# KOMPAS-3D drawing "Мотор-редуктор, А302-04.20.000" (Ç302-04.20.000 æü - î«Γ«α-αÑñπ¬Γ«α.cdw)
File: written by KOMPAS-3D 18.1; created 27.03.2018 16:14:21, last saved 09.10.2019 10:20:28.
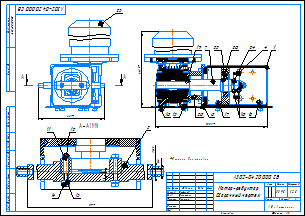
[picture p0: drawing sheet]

Sheet 1: A3, landscape

Document properties: Автор: Милов; Полное имя файла: А302-00.20.000  - Мотор-редуктор.spw; Масса: 33.945

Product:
- Part/product: Мотор-редуктор  | designation А302-04.20.000  | pos. 0
    Масса: 33.945
    Раздел спецификации: Сборочные единицы
    Форматы листов документа: 2xA3
    Примечание: @100~)2xA3
    source file: А302-04.20.000 СБ - Мотор-редуктор.cdw
  - Component [standard]: Кольцо A40.65Г ГОСТ 13942-86  | pos. 51  | Материал: Сталь 65Г ГОСТ 14959-79 (density 1000 kg/m3); Масса: 0.007267; Раздел спецификации: Стандартные изделия; additional columns: Сталь 65Г ГОСТ 14959-79
  - Component [detail]: Подшипник 80х40х18 6208-2RS1 SKF  | pos. 54  | Масса: 0.504792; Раздел спецификации: Стандартные изделия; source file: ..\..\..\..\1 ПКИ 3D\1 Крепеж стандартный\Подшипник\Подшипник 80х40х18 6208-2RS1 SKF.m3d
  - Component [standard]: Винт с цилиндрической головкой и шестигранным углублением под ключ ГОСТ Р ИСО 4762-М8 x 25-A2-70  | pos. 150  | Материал: Нержавеющая сталь (density 1000 kg/m3); Масса: 0.015; Раздел спецификации: Стандартные изделия; Рассекать на разрезах: no; additional columns: ГОСТ Р ИСО 4762-2012; М8 x 25 - A2-70
  - Component [standard]: Винт с цилиндрической головкой и шестигранным углублением под ключ ГОСТ Р ИСО 4762-М8 x 25-A2-70  | pos. 149  | Материал: Нержавеющая сталь (density 1000 kg/m3); Масса: 0.015; Раздел спецификации: Стандартные изделия; Рассекать на разрезах: no; additional columns: ГОСТ Р ИСО 4762-2012; М8 x 25 - A2-70
  - Component [standard]: Винт с цилиндрической головкой и шестигранным углублением под ключ ГОСТ Р ИСО 4762-М8 x 25-A2-70  | pos. 147  | Материал: Нержавеющая сталь (density 1000 kg/m3); Масса: 0.015; Раздел спецификации: Стандартные изделия; Рассекать на разрезах: no; additional columns: ГОСТ Р ИСО 4762-2012; М8 x 25 - A2-70
  - Component [standard]: Винт с цилиндрической головкой и шестигранным углублением под ключ ГОСТ Р ИСО 4762-М8 x 25-A2-70  | pos. 146  | Материал: Нержавеющая сталь (density 1000 kg/m3); Масса: 0.015; Раздел спецификации: Стандартные изделия; Рассекать на разрезах: no; additional columns: ГОСТ Р ИСО 4762-2012; М8 x 25 - A2-70
  - Component [standard]: Винт с цилиндрической головкой и шестигранным углублением под ключ ГОСТ Р ИСО 4762-М8 x 25-A2-70  | pos. 140  | Материал: Нержавеющая сталь (density 1000 kg/m3); Масса: 0.015; Раздел спецификации: Стандартные изделия; Рассекать на разрезах: no; additional columns: ГОСТ Р ИСО 4762-2012; М8 x 25 - A2-70
  - Component [standard]: Винт с цилиндрической головкой и шестигранным углублением под ключ ГОСТ Р ИСО 4762-М8 x 25-A2-70  | pos. 139  | Материал: Нержавеющая сталь (density 1000 kg/m3); Масса: 0.015; Раздел спецификации: Стандартные изделия; Рассекать на разрезах: no; additional columns: ГОСТ Р ИСО 4762-2012; М8 x 25 - A2-70
  - Component [standard]: Винт с цилиндрической головкой и шестигранным углублением под ключ ГОСТ Р ИСО 4762-М8 x 25-A2-70  | pos. 138  | Материал: Нержавеющая сталь (density 1000 kg/m3); Масса: 0.015; Раздел спецификации: Стандартные изделия; Рассекать на разрезах: no; additional columns: ГОСТ Р ИСО 4762-2012; М8 x 25 - A2-70
  - Component [standard]: Винт с цилиндрической головкой и шестигранным углублением под ключ ГОСТ Р ИСО 4762-М8 x 25-A2-70  | pos. 137  | Материал: Нержавеющая сталь (density 1000 kg/m3); Масса: 0.015; Раздел спецификации: Стандартные изделия; Рассекать на разрезах: no; additional columns: ГОСТ Р ИСО 4762-2012; М8 x 25 - A2-70
  - Component [standard]: Винт с цилиндрической головкой и шестигранным углублением под ключ ГОСТ Р ИСО 4762-М8 x 25-A2-70  | pos. 129  | Материал: Нержавеющая сталь (density 1000 kg/m3); Масса: 0.015; Раздел спецификации: Стандартные изделия; Рассекать на разрезах: no; additional columns: ГОСТ Р ИСО 4762-2012; М8 x 25 - A2-70
  - Component [standard]: Винт с цилиндрической головкой и шестигранным углублением под ключ ГОСТ Р ИСО 4762-М8 x 25-A2-70  | pos. 128  | Материал: Нержавеющая сталь (density 1000 kg/m3); Масса: 0.015; Раздел спецификации: Стандартные изделия; Рассекать на разрезах: no; additional columns: ГОСТ Р ИСО 4762-2012; М8 x 25 - A2-70
  - Component [standard]: Гайка М6-6H.21.12Х18Н10Т ГОСТ 5915-70  | qty 2  | Материал: Сталь 12Х18Н10Т ГОСТ 5632-72 (density 1000 kg/m3); Масса: 0.002573; Раздел спецификации: Стандартные изделия; Рассекать на разрезах: no
  - Component [standard]: Шайба 6 30Х13 019 ГОСТ 6402-70  | qty 2  | Материал: Сталь 30Х13 ГОСТ 5632-72 (density 1000 kg/m3); Масса: 0.000376; Раздел спецификации: Стандартные изделия; Рассекать на разрезах: no
  - Component [standard]: Шайба C.6.21 ГОСТ 11371-78  | qty 3  | Материал: Сталь 12Х18Н10Т ГОСТ 5632-72 (density 1000 kg/m3); Масса: 0.00099; Раздел спецификации: Стандартные изделия; Рассекать на разрезах: no
  - Component [standard]: Болт М6-6gx40 ГОСТ 7805-70  | qty 2  | Масса: 0.0112; Раздел спецификации: Стандартные изделия; Рассекать на разрезах: no
  - Component [standard]: Шайба C.6.21 ГОСТ 11371-78  | Материал: Сталь 20 ГОСТ 1050-2013 (density 1000 kg/m3); Масса: 0.00043; Раздел спецификации: Стандартные изделия; Рассекать на разрезах: no
  - Component [detail]: Вал  | designation А302-04.20.004  | pos. 3
      Материал: Сталь 40Х  ГОСТ 4543-71 (density 7825 kg/m3)
      Масса: 0.49599
      Раздел спецификации: Детали
      Форматы листов документа: A3
      Примечание: Заим.
      source file: ..\3Д\А302-00.20.004 - Вал.m3d, ..\Чертежи ПВХ\А302-03.20.004 - Вал.cdw
  - Component [detail]: Эксцентрик  | designation А302-01.20.002  | pos. 5  | Материал: Сталь 40Х  ГОСТ 4543-71 (density 7825 kg/m3); Масса: 1.91612; Раздел спецификации: Детали; Форматы листов документа: A3; source file: ..\3Д ПВХ\А302-01.20.002 - Эксцентрик.cdw, ..\3Д ПВХ\А302-01.20.002 - Эксцентрик.m3d
  - Component [assembly]: Фланец  | designation А302-04.35.000  | pos. 1  | Масса: 8.16706; Раздел спецификации: Сборочные единицы; Форматы листов документа: A2; source file: ..\3Д ПВХ\А302-01.35.000 - Фланец.a3d, ..\А302-04.00.000 - Мембранный насос ASTRA-302-PP Чертежи\А302-04.35.000 - Фланец.cdw, А302-04.35.000 - Фланец.cdw
  - Component [detail]: Основание  | designation А302-04.20.001  | pos. 4  | Материал: Сталь 20  ГОСТ 1050-2013 (density 7820 kg/m3); Масса: 2.48623; Раздел спецификации: Детали; Форматы листов документа: A3
  - Component [detail]: FB 063  | pos. 6  | Масса: 1.52018; Раздел спецификации: Детали; source file: ..\3Д ПВХ\FB 063 .m3d
- Part/product: Мотор-редуктор  | designation А302-02.20.000  | pos. 0
    Масса: 27.8186
    Раздел спецификации: Сборочные единицы
    Форматы листов документа: 2xA3
    Примечание: @100~)2xA3
  - Component [detail]: Основание  | designation А302-01.20.001  | pos. 4  | Материал: Сталь 20  ГОСТ 1050-2013 (density 7820 kg/m3); Масса: 2.48169; Раздел спецификации: Детали; Форматы листов документа: A3; source file: ..\3Д ПВХ\А302-01.20.001 - Основание.cdw, ..\3Д ПВХ\А302-01.20.001 - Основание.m3d, А302-04.20.001 - Основание.cdw
  - Component [assembly]: Фланец  | designation А302-01.35.000  | pos. 1  | Масса: 8.26617; Раздел спецификации: Сборочные единицы; Форматы листов документа: 2xA3; Примечание: @100~)2xA3; source file: ..\3Д ПВХ\А302-01.35.000 - Фланец.a3d, ..\3Д ПВХ\А302-01.35.000 - Фланец.cdw
  - Component [detail]: Эксцентрик  | designation А302-01.20.002  | pos. 5  | Материал: Сталь 40Х  ГОСТ 4543-71 (density 7825 kg/m3); Масса: 1.91612; Раздел спецификации: Детали; Форматы листов документа: A3; source file: ..\3Д ПВХ\А302-01.20.002 - Эксцентрик.cdw, ..\3Д ПВХ\А302-01.20.002 - Эксцентрик.m3d
  - Component [detail]: Вал  | designation А302-04.20.004  | pos. 3
      Материал: Сталь 40Х  ГОСТ 4543-71 (density 7825 kg/m3)
      Масса: 0.49599
      Раздел спецификации: Детали
      Форматы листов документа: A3
      Примечание: Заим.
      source file: ..\3Д\А302-00.20.004 - Вал.m3d, ..\Чертежи ПВХ\А302-03.20.004 - Вал.cdw
- Part/product: Мотор-редуктор  | designation А302-01.20.000  | pos. 0
    Масса: 27.8253
    Раздел спецификации: Сборочные единицы
    Форматы листов документа: 2xA3
    Примечание: @100~)2xA3
    source file: ..\3Д ПВХ\А302-01.20.000 - Мотор-редуктор.cdw
  - Component [standard]: Гайка М8-6H.21.12Х18Н10Т ГОСТ 5915-70  | qty 6  | Материал: Сталь 12Х18Н10Т ГОСТ 5632-72 (density 1000 kg/m3); Масса: 0.005548; Раздел спецификации: Стандартные изделия; source file: C:\Program Files\ASCON\KOMPAS-3D v18\Libs\PartLib\DATA\VAULT\methods\kompas\3d\PLib_Nut_OST92_900.m3d
  - Component [standard]: Шайба C.8.21 ГОСТ 11371-78  | qty 8  | pos. 18  | Материал: Сталь 12Х18Н10Т ГОСТ 5632-72 (density 1000 kg/m3); Масса: 0.001725; Раздел спецификации: Стандартные изделия; additional columns: Сталь 12Х18Н10Т ГОСТ 5632-72; source file: C:\Program Files\ASCON\KOMPAS-3D v18\Libs\PartLib\DATA\VAULT\methods\kompas\3d\PLib_Washer_1_712.m3d
  - Component [standard]: Шайба 8 30Х13 019 ГОСТ 6402-70  | qty 14  | Материал: Сталь 30Х13 ГОСТ 5632-72 (density 1000 kg/m3); Масса: 0.001034; Раздел спецификации: Стандартные изделия; source file: C:\Program Files\ASCON\KOMPAS-3D v18\Libs\PartLib\DATA\VAULT\methods\kompas\3d\PLib_Washer_2_712.m3d
  - Component [standard]: Винт с цилиндрической головкой и шестигранным углублением под ключ ГОСТ Р ИСО 4762 - М8 x 25 - A2-70  | qty 10  | Материал: Нержавеющая сталь (density 1000 kg/m3); Масса: 0.015; Раздел спецификации: Стандартные изделия; additional columns: ГОСТ Р ИСО 4762-2012; source file: C:\Program Files\ASCON\KOMPAS-3D v18\Libs\PartLib\DATA\VAULT\methods\kompas\3d\PLib_Screw_DIN_7984_1500.m3d
  - Component [standard]: Шайба C.8.21 ГОСТ 11371-78  | qty 12  | Материал: Сталь 12Х18Н10Т ГОСТ 5632-72 (density 1000 kg/m3); Масса: 0.001725; Раздел спецификации: Стандартные изделия; source file: C:\Program Files\ASCON\KOMPAS-3D v18\Libs\PartLib\DATA\VAULT\methods\kompas\3d\PLib_Washer_1_712.m3d
  - Component [standard]: Шпонка 8x7x90 ГОСТ 23360-78  | Масса: 0.03854; Раздел спецификации: Стандартные изделия; source file: C:\Program Files\ASCON\KOMPAS-3D v18\Libs\PartLib\DATA\VAULT\methods\kompas\3d\PLib_Key_prismatic_712.m3d
  - Component [standard]: Винт с цилиндрической головкой и шестигранным углублением под ключ ГОСТ Р ИСО 4762 - М8 x 35 - A2-70  | qty 4  | Материал: Нержавеющая сталь (density 1000 kg/m3); Масса: 0.0189; Раздел спецификации: Стандартные изделия; additional columns: ГОСТ Р ИСО 4762-2012; source file: C:\Program Files\ASCON\KOMPAS-3D v18\Libs\PartLib\DATA\VAULT\methods\kompas\3d\PLib_Screw_DIN_7984_1500.m3d
  - Component [standard]: Гайка М5-6H.5.019 ГОСТ 5915-70  | qty 2  | Масса: 0.00144; Раздел спецификации: Стандартные изделия; source file: C:\Program Files\ASCON\KOMPAS-3D v18\Libs\PartLib\DATA\VAULT\methods\kompas\3d\PLib_Nut_OST92_900.m3d
  - Component [standard]: Шайба 5 30Х13 019 ГОСТ 6402-70  | qty 2  | Материал: Сталь 30Х13 ГОСТ 5632-72 (density 1000 kg/m3); Масса: 0.000228; Раздел спецификации: Стандартные изделия; source file: C:\Program Files\ASCON\KOMPAS-3D v18\Libs\PartLib\DATA\VAULT\methods\kompas\3d\PLib_Washer_2_712.m3d
  - Component [standard]: Шайба C.5.04.019 ГОСТ 11371-78  | qty 4  | Материал: Сталь 20 ГОСТ 1050-2013 (density 1000 kg/m3); Масса: 0.00043; Раздел спецификации: Стандартные изделия; source file: C:\Program Files\ASCON\KOMPAS-3D v18\Libs\PartLib\DATA\VAULT\methods\kompas\3d\PLib_Washer_1_712.m3d
  - Component [standard]: Болт М5-6gx35.58.019 ГОСТ 7805-70  | qty 2  | Материал: Сталь 20 ГОСТ 1050-2013 (density 1000 kg/m3); Масса: 0.006685; Раздел спецификации: Стандартные изделия; source file: C:\Program Files\ASCON\KOMPAS-3D v18\Libs\PartLib\DATA\VAULT\methods\kompas\3d\PLib_Bolt_1_900.m3d
  - Component [detail]: Ползун  | designation А302-00.20.003  | pos. 2
      Материал: Полиамид П-12Б-20  ТУ 6-05-898-73 (density 1020 kg/m3)
      Масса: 0.0527789
      Раздел спецификации: Детали
      Форматы листов документа: A3
      Примечание: Заим.
      source file: ..\3Д\А302-00.20.003 - Ползун.m3d
  - Component [detail]: Вал  | designation А302-02.20.004  | pos. 3
      Материал: Сталь 40Х  ГОСТ 4543-71 (density 7825 kg/m3)
      Масса: 0.365977
      Раздел спецификации: Детали
      Форматы листов документа: A3
      Примечание: Заим.
      source file: ..\3Д\А302-00.20.004 - Вал.m3d, ..\Чертежи ПВХ\А302-02.20.004 - Вал.cdw
  - Component [detail]: Подшипник 52х25х15 62052RSH SKF  | pos. 21  | Масса: 0.182287; Раздел спецификации: Стандартные изделия; source file: ..\..\..\..\1 ПКИ 3D\1 Крепеж стандартный\Подшипник\Подшипник 52х25х15 62052RSH SKF.m3d
  - Component [standard]: Кольцо A25.65Г ГОСТ 13942-86  | qty 3  | Материал: Сталь 65Г ГОСТ 14959-79 (density 1000 kg/m3); Масса: 0.002684; Раздел спецификации: Стандартные изделия; source file: C:\Program Files\ASCON\KOMPAS-3D v18\Libs\PartLib\DATA\VAULT\methods\kompas\3d\PLib_Check_spring_rings_GOST_13942_911.m3d
  - Component [detail]: Эксцентрик  | designation А302-01.20.002  | pos. 5  | Материал: Сталь 40Х  ГОСТ 4543-71 (density 7825 kg/m3); Масса: 1.91612; Раздел спецификации: Детали; Форматы листов документа: A3; source file: ..\3Д ПВХ\А302-01.20.002 - Эксцентрик.cdw, ..\3Д ПВХ\А302-01.20.002 - Эксцентрик.m3d
  - Component [assembly]: Фланец  | designation А302-01.35.000  | pos. 1  | Масса: 8.26617; Раздел спецификации: Сборочные единицы; Форматы листов документа: 2xA3; Примечание: @100~)2xA3; source file: ..\3Д ПВХ\А302-01.35.000 - Фланец.a3d, ..\3Д ПВХ\А302-01.35.000 - Фланец.cdw
  - Component [detail]: Основание  | designation А302-01.20.001  | pos. 4  | Материал: Сталь 20  ГОСТ 1050-2013 (density 7820 kg/m3); Масса: 2.48169; Раздел спецификации: Детали; Форматы листов документа: A3; source file: ..\3Д ПВХ\А302-01.20.001 - Основание.cdw, ..\3Д ПВХ\А302-01.20.001 - Основание.m3d, А302-04.20.001 - Основание.cdw
  - Component [assembly]: Мотор-редуктор / NMRV063 N P(кВт) V5 / P(мощн./дв.), i(передат. отн.) см. заказ  | pos. 22  | Масса: 18.2; Раздел спецификации: Прочие изделия; Примечание: Двигатель / 1400 об/мин / N=1400/i; source file: ..\..\..\..\1 ПКИ 3D\Редуктора NMRW\Редукторы\Червячный мотор-редуктор NMRV063 АИР80.a3d
  - Component: Винт с цилиндрической головкой и / шестигранным углублением под ключ  / ГОСТ Р ИСО  4762-М8 x 20-6.8-A9J  | pos. 7  | Масса: 0.0134; Раздел спецификации: Стандартные изделия; additional columns: Сталь
  - Component: Шайба C.8.04.019 ГОСТ 11371-78  | qty 4  | pos. 19  | Масса: 0.001725; Раздел спецификации: Стандартные изделия; additional columns: Сталь 20 ГОСТ 1050-2013
  - Component: Винт с цилиндрической головкой /  и шестигранным углублением под ключ  / ГОСТ Р ИСО  4762-М8 x 35-A2-70  | pos. 10  | Масса: 0.0189; Раздел спецификации: Стандартные изделия; additional columns: Сталь
  - Component: Винт с цилиндрической головкой и шестигранным углублением под ключ ГОСТ Р ИСО  4762-М8 x 35-6.8-A9J  | pos. 10  | Масса: 0.0189; Раздел спецификации: Стандартные изделия; additional columns: Сталь
  - Component: Винт с цилиндрической головкой и  / шестигранным углублением под ключ  / ГОСТ Р ИСО  4762-М8 x 25-A2-70  | pos. 8  | Масса: 0.015; Раздел спецификации: Стандартные изделия; additional columns: Нержавеющая сталь
  - Component: Винт с цилиндрической головкой и шестигранным углублением под ключ ГОСТ Р ИСО  4762-М8 x 25-A2-70  | pos. 8  | Масса: 0.015; Раздел спецификации: Стандартные изделия; additional columns: Нержавеющая сталь
  - Component: Шпонка 8 x 7 x 90 ГОСТ 23360-78  | pos. 20  | Масса: 0.03854; Раздел спецификации: Стандартные изделия
  - Component: Винт с цилиндрической головкой /  и шестигранным углублением под ключ  / ГОСТ Р ИСО  4762-М8 x 35-A2-70  | pos. 9  | Масса: 0.0189; Раздел спецификации: Стандартные изделия; additional columns: Нержавеющая сталь

Title block, sheet 1: Наименование: Мотор-редуктор / Сборочный чертеж; Масса: 33,95; scale: 1:2,5; Количество листов документа: 1; organisation: АО «Астерион»; Форматы листов документа: A3; stored path: Z:\Пресс-формы\РТМ технология\Магна 32\А302-00.20.000 СБ - Мотор-редуктор.cdw; Разработал: Лифлянд; Проверил: Борисенко; Т. контр.: Лучихин

Views: Проекционный вид 2, Местный разрез 1, Разрез А-А
Referenced files in D:\Мембранные насосы\Мембранный электропривод\А302-00.00.000 - ASTRA-302 (МЭ200)\3Д\: А302-00.20.003 - Ползун.m3d, А302-00.35.001 - Труба 140х140х4.m3d, А302-00.35.002 - Пластина.m3d, А302-00.20.004 - Вал.m3d, А302-00.35.000 - Фланец.a3d, А302-00.20.002 - Эксцентрик.m3d, А302-00.20.001 - Основание.m3d
Referenced files in D:\1 ПКИ 3D\Редуктора NMRW\Редукторы\: Редуктор NMRW 063.m3d, Червячный мотор-редуктор NMRV063 АИР80.a3d
Referenced files in D:\Мембранные насосы\Мембранный электропривод\А302-00.00.000 - ASTRA-302 (МЭ200)\3Д ПВХ\: А302-01.20.001 - Основание.m3d, А302-04.35.004 - Стенка.m3d, А302-04.35.003 - Опора подшиника.m3d, FB 063 .m3d, А302-01.20.002 - Эксцентрик.m3d, А302-01.20.002 - Эксцентрик.cdw, А302-01.35.000 - Фланец.a3d
Referenced files in D:\1 ПКИ 3D\1 Крепеж стандартный\Подшипник\: Подшипник 80х40х18 6208-2RS1 SKF.m3d, Подшипник 52х25х15 62052RSH SKF.m3d
Referenced files in Z:\Мембранные насосы\Мембранный электропривод\А302-00.00.000 - ASTRA-302 (МЭ200)\3Д\: А302-00.20.000 - Мотор-редуктор.a3d, А302-00.20.002 - Эксцентрик.m3d, А302-00.20.003 - Ползун.m3d, А302-00.20.001 - Основание.m3d, А302-00.35.001 - Труба 140х140х4.m3d, А302-00.20.004 - Вал.m3d, А302-00.35.002 - Пластина.m3d
Referenced files in \\192.168.87.28\Konstructor_doc\Мембранные насосы\Мембранный электропривод\А302-00.00.000 - ASTRA-302 (МЭ200)\Чертежи\: А302-00.35.000 - Фланец.cdw
Referenced files in D:\Мембранные насосы\Мембранный электропривод\А302-00.00.000 - ASTRA-302 (МЭ200)\Чертежи\: А302-00.20.002 - Эксцентрик.cdw
Referenced files in D:\Мембранные насосы\Мембранный электропривод\А302-00.00.000 - ASTRA-302 (МЭ200)\3Д\..\Чертежи ПВХ\: А302-03.20.004 - Вал.cdw
Referenced files in D:\Мембранные насосы\Мембранный электропривод\А302-00.00.000 - ASTRA-302 (МЭ200)\3Д ПВХ\..\А302-04.00.000 - Мембранный насос ASTRA-302-PP Чертежи\: А302-04.35.000 - Фланец.cdw
Referenced files in D:\Мембранные насосы\Мембранный электропривод\А302-00.00.000 - ASTRA-302 (МЭ200)\А302-04.00.000 - Мембранный насос ASTRA-302-PP\: А302-04.35.000 - Фланец.cdw, А302-00.20.000  - Мотор-редуктор.spw
Referenced files in D:\Мембранные насосы\Мембранный электропривод\А302-00.00.000 - ASTRA-302 (МЭ200)\3Д ПВХ\Отработка\: А302-01.20.000 - Мотор-редуктор.a3d
Referenced files in D:\1 ПКИ 3D\Двигатели\АИР\: Электродвигатель АИР 80А4 IM 3081 1,1кВт 1400 об..m3d
Referenced files in C:\Program Files\ASCON\KOMPAS-3D v18\Libs\PartLib\DATA\VAULT\methods\kompas\3d\: PLib_Check_spring_rings_GOST_13942_911.m3d, PLib_Washer_1_712.m3d, PLib_Bolt_1_900.m3d, PLib_Washer_2_712.m3d, PLib_Nut_OST92_900.m3d, PLib_Screw_DIN_7984_1500.m3d, PLib_Key_prismatic_712.m3d
Referenced files in C:\Program Files\ASCON\KOMPAS-3D V16\Libs\PartLib\DATA\vault\Methods\Kompas\3D\: PLib_Check_spring_rings_GOST_13942_911.m3d, PLib_Nut_OST92_900.m3d, PLib_Key_prismatic_712.m3d
Referenced files in Z:\1 ПКИ 3D\Двигатели\АИР\: Электродвигатель АИР 80А4 IM 3081 1,1кВт 1400 об..m3d
Referenced files in Z:\1 ПКИ 3D\1 Крепеж стандартный\Подшипник\: Подшипник 52х25х15 62052RSH SKF.m3d
Referenced files in Z:\1 ПКИ 3D\Редуктора NMRW\Редукторы\: Редуктор NMRW 063.m3d
Referenced files in C:\Program Files\ASCON\KOMPAS-3D V16\Libs\PartLib\DATA\VAULT\Methods\kompas\3d\: PLib_Washer_2_712.m3d, PLib_Washer_1_712.m3d, PLib_Bolt_1_900.m3d
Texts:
  Кольцо A25.65Г ГОСТ 13942-86
  Крепежное изделие ГОСТ
  Кольцо
  ГОСТ
  3D_Doc-graphic.lyt,1.000000-4294967295-225504284413
  3D_Doc-graphic.lyt,1.000000-4294967295-225504284513
  Шайба C.5.04.019 ГОСТ 11371-78
  Шайба
  3D_Doc-graphic.lyt,1.000000-4294967295-225504285013
  Болт М5-6gx35.58.019 ГОСТ 7805-70
  Болт
  3D_Doc-graphic.lyt,1.000000-4294967295-225504285113
  3D_Doc-graphic.lyt,1.000000-4294967295-225504285213
  Шайба 5 30Х13 019 ГОСТ 6402-70
  3D_Doc-graphic.lyt,1.000000-4294967295-225504285313
  Гайка М5-6H.5.019 ГОСТ 5915-70
  Гайка
  3D_Doc-graphic.lyt,1.000000-4294967295-225504285413
  Шайба C.8.04.019 ГОСТ 11371-78
  3D_Doc-graphic.lyt,1.000000-4294967295-225504286013
  Шайба 8 30Х13 019 ГОСТ 6402-70
  3D_Doc-graphic.lyt,1.000000-4294967295-225504286113
  Винт с цилиндрической головкой и
  шестигранным углублением под ключ
  ГОСТ Р ИСО  4762-М8 x 20-6.8-A9J
  Винт с цилиндрической головкой и шестигранным углублением под ключ
  Р ИСО
  Сталь
  3D_Doc-graphic.lyt,1.000000-4294967295-225504286213
  3D_Doc-graphic.lyt,1.000000-4294967295-225504287213
  3D_Doc-graphic.lyt,1.000000-4294967295-225504287313
  ГОСТ Р ИСО  4762-М8 x 35-6.8-A9J
  3D_Doc-graphic.lyt,1.000000-4294967295-225504287413
  3D_Doc-graphic.lyt,1.000000-4294967295-225504287513
  Гайка М8-6H.5.019 ГОСТ 5915-70
  3D_Doc-graphic.lyt,1.000000-4294967295-225504287613
  3D_Doc-graphic.lyt,1.000000-4294967295-225504289213
  3D_Doc-graphic.lyt,1.000000-4294967295-225504289313
  Винт с цилиндрической головкой и шестигранным углублением под ключ ГОСТ Р ИСО  4762-М8 x 35-6.8-A9J
  3D_Doc-graphic.lyt,1.000000-4294967295-225504289413
  3D_Doc-graphic.lyt,1.000000-4294967295-225504289513
  3D_Doc-graphic.lyt,1.000000-4294967295-225504289613
  NMRV063 N P(кВт) V5
  P(мощн./дв.), i(передат. отн.) см. заказ
  Мотор-редуктор / NMRV063 N P(кВт) V5 / P(мощн./дв.), i(передат. отн.) см. заказ
  Двигатель
  Двигатель / 1400 об/мин / N=1400/i
  Фланец
  Эксцентрик
  Подшипник 52х25х15 62052RSH SKF
  Подшипник
  RSH
  SKF
  Вал
  Ползун
  Шпонка 8 x 7 x 90 ГОСТ 23360-78
  Шпонка
  Основание
  Полипропилен  ГОСТ 26996-86
  Винт с цилиндрической головкой и шестигранным углублением под ключ ГОСТ Р ИСО 4762-М8 x 25-A2-70
  ГОСТ Р ИСО
  Шайба C.8.21 ГОСТ 11371-78
  Заим.
  Гайка М8-6H.21.12Х18Н10Т ГОСТ 5915-70
  FB 063
  Подшипник 80х40х18 6208-2RS1 SKF
  Кольцо A40.65Г ГОСТ 13942-86
  Электродвигатель / АИР 80А4 IM 3081 1,1кВт 1400 об/мин
  Редуктор NMRW 063
  Пластина
  Труба 140х140х6
  Опора подшипника
  Стенка
  Шайба C.6.21 ГОСТ 11371-78
  Болт М6-6gx40 ГОСТ 7805-70
  Шайба 6 30Х13 019 ГОСТ 6402-70
  Гайка М6-6H.21.12Х18Н10Т ГОСТ 5915-70
  Винт с цилиндрической головкой и шестигранным углублением под ключ ГОСТ Р ИСО 4762 - М8 x 25 - A2-70
  Шпонка 8x7x90 ГОСТ 23360-78
Dimensions and other numbers on the sheet: 442,5; 4; 7; 388,9; 6; 10; 15; 16; 17; 18; 19; 20; 1; 24; 25; 26; 58; 65Г; 019; 2; 04; 40Х; 3; 30Х13; 5; 12; 8; 6.8; 1400 об/мин; 78; 21; 12Х18Н10Т; 1:2,5; 33,95

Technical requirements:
  *Размеры для справок.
